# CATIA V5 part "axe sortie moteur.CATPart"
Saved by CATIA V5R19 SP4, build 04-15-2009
Part number: axe sortie moteur
Bounding box of the stored display mesh (mm): x 0 to 35.48, y 4.823 to 12.523, z 11.051 to 18.374
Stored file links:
  G:\EU_thinkMotion\CFAO_2010\MMS_groupe1\MMS_groupe1\A reprendre\OK\rdeneffle\axe sortie moteur.CATPart
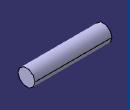
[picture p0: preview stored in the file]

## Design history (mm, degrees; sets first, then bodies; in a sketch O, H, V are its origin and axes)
Body1 (main body)
  Sketch1 on yz-plane, origin (0, 0, 0), H (0, 1, 0), V (0, 0, 1)
    circle A1 centre (8.6732, 14.7123) radius 3.85
    radius A1 = 3.85
  Pad1: profile Sketch1, direction (1, 0, 0), length 35.48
